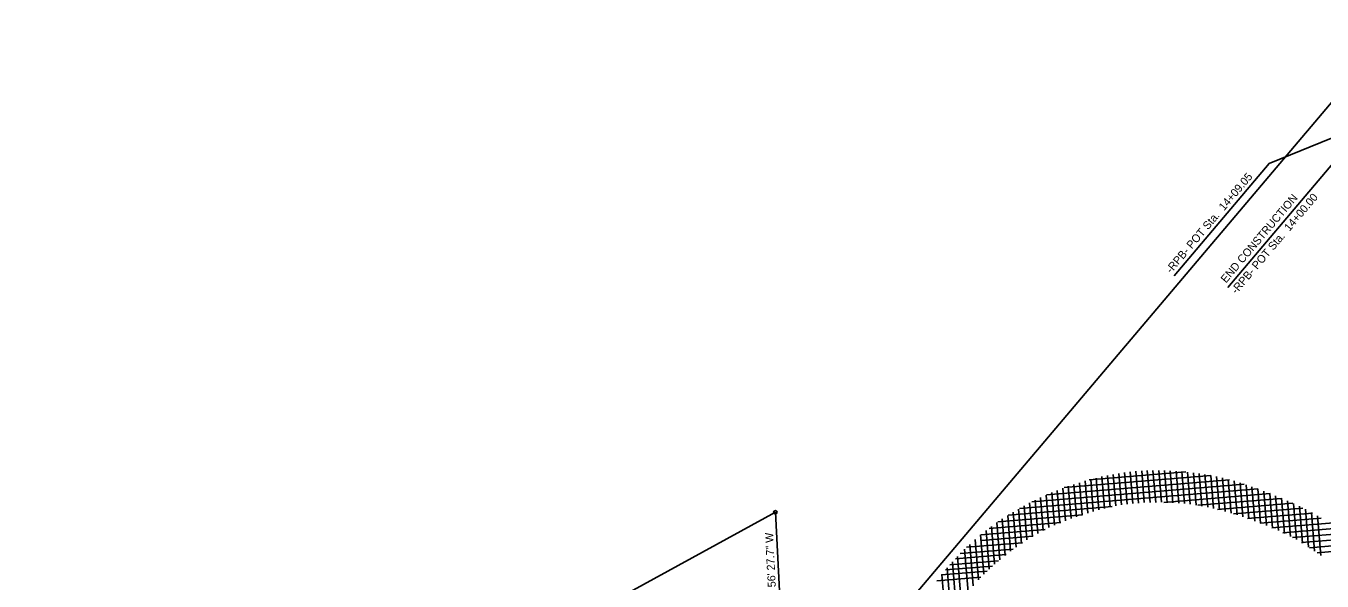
# Model space of a CAD drawing. Extents: x 1761082 to 1764358, y 421907 to 425434.
# Drawn here: x 1761204 to 1762338, y 423541 to 424026 of the extents above; entities that cross this region are included whole.
import ezdxf

# ---------------------------------------------------------------- set-up
doc = ezdxf.new("R2010")
doc.units = 0
for name, color, linetype in [('MARK HOOKS CENTER LEFT TURN ARROW CELL', 7, 'Continuous'), ('MARK STRAIGHT RIGHT ARROW CELL', 7, 'Continuous'), ('MARK UTURN ARROW CELL', 7, 'Continuous'), ('Prop Conc 4in Sidewalk', 7, 'Continuous'), ('Prop Mkg 3ft Min Skp 3ft Wide White', 7, 'Continuous'), ('Prop Mkg Solid White Multiple Diagonals V8i', 7, 'Continuous')]:
    doc.layers.add(name, color=color, linetype=linetype)

msp = doc.modelspace()

# ---------------------------------------------------------------- linework, layer by layer
at = {"layer": 'MARK STRAIGHT RIGHT ARROW CELL'}
msp.add_line((1761859.3, 423600.9), (1761864.2, 423504.7), dxfattribs=at)
at = {"layer": 'MARK UTURN ARROW CELL'}
for points in [[(1762355.2, 423931.6), (1762291.3, 423905.7), (1762208.3, 423807.7)], [(1762356.7, 423917.1), (1762340.7, 423898.2), (1762255.3, 423797.4)], [(1761859.3, 423600.9), (1761701.3, 423514.3), (1761619.7, 423418.1)]]:
    msp.add_lwpolyline(points, dxfattribs=at)
msp.add_circle((1761859.3, 423600.9), 1.5, dxfattribs=at)
at = {"layer": 'Prop Conc 4in Sidewalk'}
for p, q in [((1762112.1, 423622.4), (1762240.3, 423633)), ((1762133.9, 423629.2), (1762218.5, 423636.2)), ((1762142.4, 423603), (1762140.1, 423630.8)), ((1762147.3, 423604.2), (1762145, 423632)), ((1762152.3, 423605.4), (1762150, 423633)), ((1762157.2, 423606.5), (1762154.9, 423634)), ((1762162.1, 423607.3), (1762159.9, 423634.8)), ((1762167.1, 423608), (1762164.8, 423635.5)), ((1762172.1, 423608.5), (1762169.8, 423636.1)), ((1762177.1, 423608.9), (1762174.8, 423636.7)), ((1762182, 423609.3), (1762179.8, 423637)), ((1762187.1, 423609.4), (1762184.7, 423637.3)), ((1762192.1, 423609.5), (1762189.7, 423637.4)), ((1762197.1, 423609.6), (1762194.8, 423637.4)), ((1762202.1, 423609.5), (1762199.8, 423637.3)), ((1762207.1, 423609.2), (1762204.8, 423637.2)), ((1762212.2, 423608.9), (1762209.9, 423636.9)), ((1762217.2, 423608.5), (1762214.9, 423636.6)), ((1762222.3, 423607.9), (1762220, 423636)), ((1762227.4, 423607.2), (1762225, 423635.4)), ((1762232.5, 423606.3), (1762230.1, 423634.8)), ((1762237.6, 423605.3), (1762235.2, 423633.9)), ((1762242.7, 423604.2), (1762240.3, 423633)), ((1762247.8, 423603), (1762245.4, 423632)), ((1762252.9, 423601.6), (1762250.5, 423630.9)), ((1762072.8, 423604.1), (1762281.3, 423621.3)), ((1762083.6, 423610), (1762269.5, 423625.4)), ((1762096.5, 423616.1), (1762256.6, 423629.3)), ((1762108.2, 423591.7), (1762105.9, 423620)), ((1762113.1, 423593.5), (1762110.8, 423621.9)), ((1762118, 423595.3), (1762115.6, 423623.6)), ((1762122.9, 423596.9), (1762120.5, 423625.2)), ((1762127.7, 423598.5), (1762125.4, 423626.7)), ((1762132.6, 423600.1), (1762130.3, 423628.2)), ((1762137.5, 423601.6), (1762135.2, 423629.6)), ((1762258.1, 423600.2), (1762255.6, 423629.6)), ((1762263.2, 423598.6), (1762260.8, 423628.2)), ((1762268.4, 423596.9), (1762265.9, 423626.6)), ((1762273.5, 423595.1), (1762271.1, 423624.9)), ((1762278.7, 423593.2), (1762276.2, 423623.1)), ((1762283.9, 423591.2), (1762281.4, 423621.3)), ((1762289.1, 423589.2), (1762286.6, 423619.4)), ((1762084.2, 423579.6), (1762081.7, 423609)), ((1762088.9, 423582.4), (1762086.5, 423611.5)), ((1762093.7, 423585), (1762091.4, 423613.8)), ((1762098.6, 423587.4), (1762096.2, 423615.9)), ((1762103.4, 423589.7), (1762101.1, 423618)), ((1762199.3, 423609.5), (1762292.1, 423617.2)), ((1762228.9, 423607), (1762302.2, 423613)), ((1762246.1, 423603.4), (1762312.1, 423608.8)), ((1762294.3, 423587), (1762291.8, 423617.3)), ((1762299.5, 423584.8), (1762296.9, 423615.2)), ((1762304.7, 423582.4), (1762302.1, 423613.1)), ((1762309.9, 423579.8), (1762307.3, 423610.9)), ((1762315.2, 423577), (1762312.5, 423608.6)), ((1762054, 423592.5), (1762128, 423598.6)), ((1762065.1, 423566.8), (1762062.6, 423598.1)), ((1762062.9, 423598.2), (1762154, 423605.8)), ((1762069.9, 423570.3), (1762067.3, 423601)), ((1762074.6, 423573.6), (1762072.1, 423603.7)), ((1762079.4, 423576.7), (1762076.9, 423606.4)), ((1762260.2, 423599.5), (1762320.9, 423604.5)), ((1762272.3, 423595.5), (1762329.2, 423600.2)), ((1762283.4, 423591.4), (1762336.9, 423595.8)), ((1762320.4, 423573.8), (1762317.8, 423606.1)), ((1762325.7, 423570.4), (1762323, 423603.5)), ((1762331, 423566.9), (1762328.3, 423600.7)), ((1762336.4, 423563.2), (1762333.5, 423597.8)), ((1762039.2, 423581.2), (1762095.5, 423585.9)), ((1762046.4, 423551.2), (1762043.6, 423584.8)), ((1762046.3, 423586.8), (1762109.2, 423592)), ((1762051, 423555.4), (1762048.3, 423588.4)), ((1762055.7, 423559.4), (1762053, 423591.8)), ((1762060.4, 423563.2), (1762057.8, 423595)), ((1762293.7, 423587.2), (1762358.6, 423592.6)), ((1762303.4, 423583), (1762361.9, 423587.9)), ((1762026.6, 423570.2), (1762075.5, 423574.2)), ((1762037.1, 423541.8), (1762034.2, 423577)), ((1762041.7, 423546.6), (1762038.9, 423581)), ((1762039.6, 423576.3), (1762084.7, 423580)), ((1762311.9, 423578.7), (1762365.3, 423583.1)), ((1762319.6, 423574.3), (1762368.6, 423578.4)), ((1762326.6, 423569.9), (1762372, 423573.7)), ((1762016.8, 423560.2), (1762061.2, 423563.9)), ((1762022, 423523.2), (1762018.8, 423562.3)), ((1762021, 423564.7), (1762067.4, 423568.5)), ((1762028, 423531.1), (1762024.9, 423568.6)), ((1762032.5, 423536.6), (1762029.5, 423572.8)), ((1762333.2, 423565.4), (1762375.4, 423568.9)), ((1762008.1, 423550.4), (1762049.2, 423553.8)), ((1762013.1, 423509.9), (1762009.6, 423552.2)), ((1762011.9, 423554.9), (1762054.5, 423558.4)), ((1762017.5, 423516.8), (1762014.2, 423557.4)), ((1762000.7, 423540.8), (1762039.2, 423544)), ((1762004.8, 423546.2), (1762044.6, 423549.5)), ((1762008.7, 423502.6), (1762005, 423546.5))]:
    msp.add_line(p, q, dxfattribs=at)
at = {"layer": 'Prop Mkg 3ft Min Skp 3ft Wide White'}
msp.add_line((1761864.2, 423504.6), (1761859.3, 423600.9), dxfattribs=at)
at = {"layer": 'Prop Mkg Solid White Multiple Diagonals V8i'}
msp.add_line((1761203.6, 422611), (1763595.3, 425434.2), dxfattribs=at)

# ---------------------------------------------------------------- texts
at = {"layer": 'MARK HOOKS CENTER LEFT TURN ARROW CELL'}
msp.add_text('N 2%%d 56\' 27.7" W', height=7, rotation=92.941, dxfattribs=at).set_placement((1761860.8, 423514.6))
at = {"layer": 'MARK UTURN ARROW CELL'}
for s, p in [('-RPB- POT Sta.  14+09.05', (1762205.5, 423809.2)), ('END CONSTRUCTION', (1762253.6, 423800.8)), ('-RPB- POT Sta.  14+00.00', (1762262.7, 423791.2))]:
    msp.add_text(s, height=7, rotation=49.7301, dxfattribs=at).set_placement(p)

doc.saveas('drawing.dxf')
